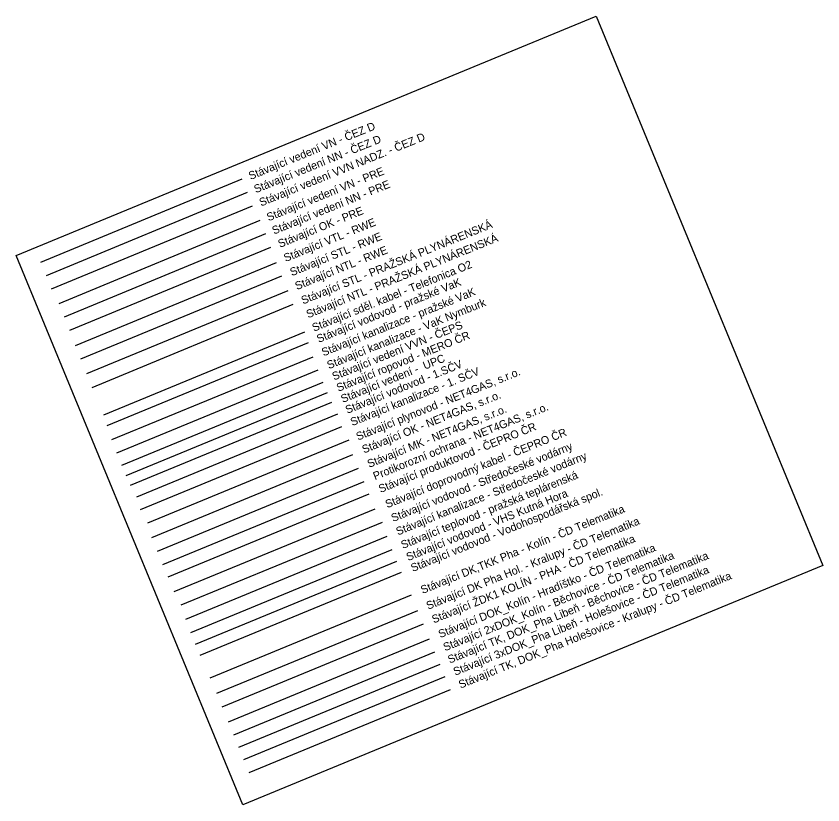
# Model space of a CAD drawing. Extents: x -748507 to -687366, y -1057342 to -1024924.
# Drawn here: x -746307.9 to -746022.3, y -1026293.5 to -1026014.2 of the extents above; entities that cross this region are included whole.
import ezdxf

# ---------------------------------------------------------------- set-up
doc = ezdxf.new("R2010")
doc.units = 0
for name, color, linetype in [('2xDOK_Kolín - Pha Běchovice - ČD Telematika', 7, 'Continuous'), ('3xDOK_Pha Libeň - Holešovice', 7, 'Continuous'), ('DK - PHA - KOLÍN - ČD TELEMATIKA', 7, 'Continuous'), ('DK - Pha Holešovice - Kralupy - ČD TELEMATIKA', 7, 'Continuous'), ('DOK_Kolín - Hradištko - ČD Telematika', 7, 'Continuous'), ('Kanalizace - 1 SČV', 7, 'Continuous'), ('Kanalizace - pražské vodovody a kanalizace', 7, 'Continuous'), ('Kanalizace - Středočeské vodárny', 7, 'Continuous'), ('Kanalizace - VaK Nymburk', 7, 'Continuous'), ('MK - NET4GAS', 7, 'Continuous'), ('NTL - PRAŽSKÁ PLYNÁRENSKÁ', 7, 'Continuous'), ('OK - NET4GAS', 7, 'Continuous'), ('Plynovod - NET4GAS', 7, 'Continuous'), ('PRE - NN', 7, 'Continuous'), ('PRE - OK', 7, 'Continuous'), ('PRE - VN', 7, 'Continuous'), ('pRODUKTOVOD - ČEPRO ČR', 7, 'Continuous'), ('Protikorozní ochrana - NET4GAS', 7, 'Continuous'), ('Ropovod - MERO ČR', 7, 'Continuous'), ('RWE - NTL', 7, 'Continuous'), ('RWE - STL', 7, 'Continuous'), ('RWE - VTL', 7, 'Continuous'), ('STL - PRAŽSKÁ PLYNÁRENSKÁ', 7, 'Continuous'), ('Telefonica O2', 7, 'Continuous'), ('Teplovod - Pražská teplárenská', 7, 'Continuous'), ('TK+DOK_Pha Holešovice - Kralupy', 7, 'Continuous'), ('TK+DOK_Pha Libeň - Běchovice', 7, 'Continuous'), ('UPC sdělovací kabel', 7, 'Continuous'), ('Vodovod - 1 SČV', 7, 'Continuous'), ('Vodovod - přežsko vodovody a kanalizace', 7, 'Continuous'), ('Vodovod - Středočeské vodárny', 7, 'Continuous'), ('Vodovod - VHS Kutná Hora', 7, 'Continuous'), ('Vodovod - Vodohospodářská společnost', 7, 'Continuous'), ('ČEPS - VVN', 7, 'Continuous'), ('ČEZ Distribuce - NN', 7, 'Continuous'), ('ČEZ Distribuce - VN', 7, 'Continuous'), ('ČEZ Distribuce - VVN', 7, 'Continuous'), ('ŽDK1 - KOLÍN - PHA - ČD TELEMATIKA', 7, 'Continuous')]:
    doc.layers.add(name, color=color, linetype=linetype)

msp = doc.modelspace()

# ---------------------------------------------------------------- linework, layer by layer
at = {"layer": '2xDOK_Kolín - Pha Běchovice - ČD Telematika'}
msp.add_line((-746230.86, -1026268.72), (-746159.63, -1026239.33), dxfattribs=at)
at = {"layer": '3xDOK_Pha Libeň - Holešovice'}
msp.add_line((-746227.28, -1026277.41), (-746156.05, -1026248.03), dxfattribs=at)
at = {"layer": 'DK - PHA - KOLÍN - ČD TELEMATIKA'}
msp.add_line((-746239.18, -1026248.52), (-746167.95, -1026219.13), dxfattribs=at)
at = {"layer": 'DK - Pha Holešovice - Kralupy - ČD TELEMATIKA'}
msp.add_line((-746236.92, -1026254.01), (-746165.69, -1026224.63), dxfattribs=at)
at = {"layer": 'DOK_Kolín - Hradištko - ČD Telematika'}
msp.add_line((-746232.76, -1026264.11), (-746161.53, -1026234.73), dxfattribs=at)
at = {"layer": 'Kanalizace - 1 SČV'}
msp.add_line((-746192.72, -1026159.67), (-746263.96, -1026189.03), dxfattribs=at)
at = {"layer": 'Kanalizace - pražské vodovody a kanalizace'}
msp.add_line((-746202.92, -1026134.92), (-746274.16, -1026164.27), dxfattribs=at)
at = {"layer": 'Kanalizace - Středočeské vodárny'}
msp.add_line((-746176.73, -1026198.48), (-746247.97, -1026227.84), dxfattribs=at)
at = {"layer": 'Kanalizace - VaK Nymburk'}
msp.add_line((-746272.26, -1026168.86), (-746201.03, -1026139.51), dxfattribs=at)
at = {"layer": 'MK - NET4GAS'}
msp.add_line((-746257.93, -1026203.66), (-746186.69, -1026174.31), dxfattribs=at)
at = {"layer": 'NTL - PRAŽSKÁ PLYNÁRENSKÁ'}
msp.add_lwpolyline([(-746307.94, -1026098.96), (-746102.59, -1026014.19), (-746022.27, -1026208.75), (-746227.62, -1026293.52)], close=True, dxfattribs=at)
at = {"layer": 'OK - NET4GAS'}
msp.add_line((-746259.92, -1026198.82), (-746188.68, -1026169.47), dxfattribs=at)
at = {"layer": 'Plynovod - NET4GAS'}
msp.add_line((-746261.25, -1026193.64), (-746190.04, -1026164.21), dxfattribs=at)
at = {"layer": 'PRE - NN'}
msp.add_line((-746290.78, -1026120.63), (-746219.57, -1026091.2), dxfattribs=at)
at = {"layer": 'PRE - OK'}
msp.add_line((-746288.98, -1026125.41), (-746217.78, -1026095.98), dxfattribs=at)
at = {"layer": 'PRE - VN'}
msp.add_line((-746292.73, -1026115.91), (-746221.52, -1026086.48), dxfattribs=at)
at = {"layer": 'pRODUKTOVOD - ČEPRO ČR'}
for p, q in [((-746254.16, -1026212.82), (-746182.95, -1026183.38)), ((-746252.03, -1026217.98), (-746180.79, -1026188.63))]:
    msp.add_line(p, q, dxfattribs=at)
at = {"layer": 'Protikorozní ochrana - NET4GAS'}
msp.add_line((-746255.99, -1026208.38), (-746184.75, -1026179.02), dxfattribs=at)
at = {"layer": 'Ropovod - MERO ČR'}
msp.add_line((-746268.95, -1026176.91), (-746197.74, -1026147.48), dxfattribs=at)
at = {"layer": 'RWE - NTL'}
msp.add_line((-746282.86, -1026140.79), (-746211.65, -1026111.36), dxfattribs=at)
at = {"layer": 'RWE - STL'}
msp.add_line((-746285.03, -1026135.55), (-746213.82, -1026106.12), dxfattribs=at)
at = {"layer": 'RWE - VTL'}
msp.add_line((-746286.97, -1026130.85), (-746215.76, -1026101.41), dxfattribs=at)
at = {"layer": 'STL - PRAŽSKÁ PLYNÁRENSKÁ'}
msp.add_line((-746281.01, -1026145.68), (-746209.81, -1026116.25), dxfattribs=at)
at = {"layer": 'Telefonica O2'}
msp.add_line((-746276.92, -1026155.42), (-746205.71, -1026125.99), dxfattribs=at)
at = {"layer": 'Teplovod - Pražská teplárenská'}
msp.add_line((-746246.08, -1026232.44), (-746174.84, -1026203.08), dxfattribs=at)
at = {"layer": 'TK+DOK_Pha Holešovice - Kralupy'}
msp.add_line((-746225.38, -1026282.01), (-746154.15, -1026252.63), dxfattribs=at)
at = {"layer": 'TK+DOK_Pha Libeň - Běchovice'}
msp.add_line((-746229.07, -1026273.06), (-746157.84, -1026243.68), dxfattribs=at)
at = {"layer": 'UPC sdělovací kabel'}
msp.add_line((-746267.4, -1026180.28), (-746196.17, -1026150.9), dxfattribs=at)
at = {"layer": 'Vodovod - 1 SČV'}
msp.add_line((-746265.24, -1026184.39), (-746194, -1026155.04), dxfattribs=at)
at = {"layer": 'Vodovod - přežsko vodovody a kanalizace'}
msp.add_line((-746275.65, -1026159.13), (-746204.41, -1026129.78), dxfattribs=at)
at = {"layer": 'Vodovod - Středočeské vodárny'}
msp.add_line((-746249.46, -1026222.7), (-746178.22, -1026193.35), dxfattribs=at)
at = {"layer": 'Vodovod - VHS Kutná Hora'}
msp.add_line((-746244.38, -1026236.6), (-746173.14, -1026207.24), dxfattribs=at)
at = {"layer": 'Vodovod - Vodohospodářská společnost'}
msp.add_line((-746242.76, -1026240.51), (-746171.52, -1026211.16), dxfattribs=at)
at = {"layer": 'ČEPS - VVN'}
msp.add_line((-746270.46, -1026173.25), (-746199.25, -1026143.82), dxfattribs=at)
at = {"layer": 'ČEZ Distribuce - NN'}
msp.add_line((-746297.21, -1026105.99), (-746226, -1026076.56), dxfattribs=at)
at = {"layer": 'ČEZ Distribuce - VN'}
msp.add_line((-746299.16, -1026101.27), (-746227.95, -1026071.84), dxfattribs=at)
at = {"layer": 'ČEZ Distribuce - VVN'}
msp.add_line((-746295.41, -1026110.78), (-746224.2, -1026081.35), dxfattribs=at)
at = {"layer": 'ŽDK1 - KOLÍN - PHA - ČD TELEMATIKA'}
msp.add_line((-746234.93, -1026258.83), (-746163.7, -1026229.45), dxfattribs=at)

# ---------------------------------------------------------------- texts
at = {"layer": '2xDOK_Kolín - Pha Běchovice - ČD Telematika'}
msp.add_text('Stávající 2xDOK_Kolín - Běchovice - ČD Telematika', height=2.8334, rotation=22.0228, dxfattribs=at).set_placement((-746156.03, -1026239.14))
at = {"layer": '3xDOK_Pha Libeň - Holešovice'}
msp.add_text('Stávající 3xDOK_Pha Libeň - Holešovice - ČD Telematika', height=2.8334, rotation=22.0228, dxfattribs=at).set_placement((-746152.46, -1026247.8))
at = {"layer": 'DK - PHA - KOLÍN - ČD TELEMATIKA'}
msp.add_text('Stávající DK,TKK Pha - Kolín - ČD Telematika', height=2.8334, rotation=22.0228, dxfattribs=at).set_placement((-746164, -1026218.84))
at = {"layer": 'DK - Pha Holešovice - Kralupy - ČD TELEMATIKA'}
msp.add_text('Stávající DK Pha Hol. - Kralupy - ČD Telematika', height=2.8334, rotation=22.0228, dxfattribs=at).set_placement((-746162.03, -1026224.45))
at = {"layer": 'DOK_Kolín - Hradištko - ČD Telematika'}
msp.add_text('Stávající DOK_Kolín - Hradíštko - ČD Telematika', height=2.8334, rotation=22.0228, dxfattribs=at).set_placement((-746157.73, -1026234.48))
at = {"layer": 'Kanalizace - 1 SČV'}
msp.add_text('Stávající kanalizace - 1. SČV', height=2.8334, rotation=21.9993, dxfattribs=at).set_placement((-746188.88, -1026159.38))
at = {"layer": 'Kanalizace - pražské vodovody a kanalizace'}
msp.add_text('Stávající kanalizace - pražské VaK', height=2.8334, rotation=21.9993, dxfattribs=at).set_placement((-746199.09, -1026134.7))
at = {"layer": 'Kanalizace - Středočeské vodárny'}
msp.add_text('Stávající kanalizace - Středočeské vodárny', height=2.8334, rotation=21.9993, dxfattribs=at).set_placement((-746172.74, -1026198.13))
at = {"layer": 'Kanalizace - VaK Nymburk'}
msp.add_text('Stávající kanalizace - VaK Nymburk', height=2.8334, rotation=21.9993, dxfattribs=at).set_placement((-746197.19, -1026139.24))
at = {"layer": 'MK - NET4GAS'}
msp.add_text('Stávající MK - NET4GAS, s.r.o.', height=2.8334, rotation=21.9993, dxfattribs=at).set_placement((-746182.91, -1026174.2))
at = {"layer": 'NTL - PRAŽSKÁ PLYNÁRENSKÁ'}
msp.add_text('Stávající NTL - PRAŽSKÁ PLYNÁRENSKÁ', height=2.8334, rotation=22.0624, dxfattribs=at).set_placement((-746204.52, -1026121.22))
at = {"layer": 'OK - NET4GAS'}
msp.add_text('Stávající OK - NET4GAS, s.r.o.', height=2.8334, rotation=21.9993, dxfattribs=at).set_placement((-746184.77, -1026169.1))
at = {"layer": 'Plynovod - NET4GAS'}
msp.add_text('Stávající plynovod - NET4GAS, s.r.o.', height=2.8334, rotation=21.9993, dxfattribs=at).set_placement((-746186.86, -1026164.53))
at = {"layer": 'PRE - NN'}
msp.add_text('Stávající vedení NN - PRE', height=2.8334, rotation=22.0624, dxfattribs=at).set_placement((-746216.62, -1026091.57))
at = {"layer": 'PRE - OK'}
msp.add_text('Stávající OK - PRE', height=2.8334, rotation=22.0624, dxfattribs=at).set_placement((-746214.53, -1026096.27))
at = {"layer": 'PRE - VN'}
msp.add_text('Stávající vedení VN - PRE', height=2.8334, rotation=22.0624, dxfattribs=at).set_placement((-746218.52, -1026086.87))
at = {"layer": 'pRODUKTOVOD - ČEPRO ČR'}
for s, p in [('Stávající produktovod - ČEPRO ČR ', (-746178.92, -1026183.08)), ('Stávající doprovodný kabel - ČEPRO ČR ', (-746176.52, -1026188.49))]:
    msp.add_text(s, height=2.8334, rotation=22.0624, dxfattribs=at).set_placement(p)
at = {"layer": 'Protikorozní ochrana - NET4GAS'}
msp.add_text('Protikorozní ochrana - NET4GAS, s.r.o.', height=2.8334, rotation=21.9993, dxfattribs=at).set_placement((-746180.85, -1026178.55))
at = {"layer": 'Ropovod - MERO ČR'}
msp.add_text('Stávající ropovod - MERO ČR ', height=2.8334, rotation=22.0624, dxfattribs=at).set_placement((-746193.81, -1026147.25))
at = {"layer": 'RWE - NTL'}
msp.add_text('Stávající NTL - RWE', height=2.8334, rotation=22.0624, dxfattribs=at).set_placement((-746208.5, -1026111.22))
at = {"layer": 'RWE - STL'}
msp.add_text('Stávající STL - RWE', height=2.8334, rotation=22.0624, dxfattribs=at).set_placement((-746210.29, -1026106.31))
at = {"layer": 'RWE - VTL'}
msp.add_text('Stávající VTL - RWE', height=2.8334, rotation=22.0624, dxfattribs=at).set_placement((-746212.49, -1026101.28))
at = {"layer": 'STL - PRAŽSKÁ PLYNÁRENSKÁ'}
msp.add_text('Stávající STL - PRAŽSKÁ PLYNÁRENSKÁ', height=2.8334, rotation=22.0624, dxfattribs=at).set_placement((-746206.31, -1026116.31))
at = {"layer": 'Telefonica O2'}
msp.add_text('Stávající sděl. kabel - Telefonica O2', height=2.8334, rotation=22.0624, dxfattribs=at).set_placement((-746202.45, -1026125.97))
at = {"layer": 'Teplovod - Pražská teplárenská'}
msp.add_text('Stávající teplovod - pražská teplárenská', height=2.8334, rotation=21.9993, dxfattribs=at).set_placement((-746171.01, -1026202.92))
at = {"layer": 'TK+DOK_Pha Holešovice - Kralupy'}
msp.add_text('Stávající TK, DOK_Pha Holešovice - Kralupy - ČD Telematika', height=2.8334, rotation=22.0228, dxfattribs=at).set_placement((-746150.57, -1026252.38))
at = {"layer": 'TK+DOK_Pha Libeň - Běchovice'}
msp.add_text('Stávající TK, DOK_Pha Libeň - Běchovice - ČD Telematika', height=2.8334, rotation=22.0228, dxfattribs=at).set_placement((-746154.41, -1026243.51))
at = {"layer": 'UPC sdělovací kabel'}
msp.add_text('Stávající vedení -  UPC', height=2.8334, rotation=22.0228, dxfattribs=at).set_placement((-746192.28, -1026151.19))
at = {"layer": 'Vodovod - 1 SČV'}
msp.add_text('Stávající vodovod - 1.SČV', height=2.8334, rotation=21.9993, dxfattribs=at).set_placement((-746190.67, -1026155.06))
at = {"layer": 'Vodovod - přežsko vodovody a kanalizace'}
msp.add_text('Stávající vodovod - pražské VaK', height=2.8334, rotation=21.9993, dxfattribs=at).set_placement((-746200.82, -1026129.94))
at = {"layer": 'Vodovod - Středočeské vodárny'}
msp.add_text('Stávající vodovod - Středočeské vodárny', height=2.8334, rotation=21.9993, dxfattribs=at).set_placement((-746174.47, -1026193.37))
at = {"layer": 'Vodovod - VHS Kutná Hora'}
msp.add_text('Stávající vodovod - VHS Kutná Hora', height=2.8334, rotation=21.9993, dxfattribs=at).set_placement((-746169.12, -1026207.19))
at = {"layer": 'Vodovod - Vodohospodářská společnost'}
msp.add_text('Stávající vodovod - Vodohospodářská spol.', height=2.8334, rotation=21.9993, dxfattribs=at).set_placement((-746167.5, -1026211.05))
at = {"layer": 'ČEPS - VVN'}
msp.add_text('Stávající vedení VVN - ČEPS', height=2.8334, rotation=22.0624, dxfattribs=at).set_placement((-746195.37, -1026143.24))
at = {"layer": 'ČEZ Distribuce - NN'}
msp.add_text('Stávající vedení NN - ČEZ D', height=2.8334, rotation=22.0624, dxfattribs=at).set_placement((-746223.06, -1026076.92))
at = {"layer": 'ČEZ Distribuce - VN'}
msp.add_text('Stávající vedení VN - ČEZ D', height=2.8334, rotation=22.0624, dxfattribs=at).set_placement((-746224.95, -1026072.23))
at = {"layer": 'ČEZ Distribuce - VVN'}
msp.add_text('Stávající vedení VVN NADZ. - ČEZ D', height=2.8334, rotation=22.0624, dxfattribs=at).set_placement((-746221.17, -1026081.62))
at = {"layer": 'ŽDK1 - KOLÍN - PHA - ČD TELEMATIKA'}
msp.add_text('Stávající ŽDK1 KOLÍN - PHA - ČD Telematika', height=2.8334, rotation=22.0228, dxfattribs=at).set_placement((-746160.05, -1026229.28))

doc.saveas('drawing.dxf')
